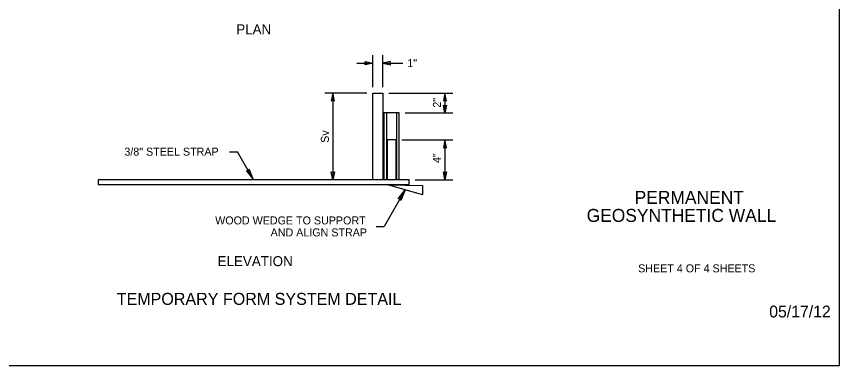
# Model space of a CAD drawing. Extents: x 99862 to 103151, y 100000 to 111076.
# Drawn here: x 101506 to 103151, y 109000 to 109698 of the extents above; entities that cross this region are included whole.
import ezdxf

# ---------------------------------------------------------------- set-up
doc = ezdxf.new("R2010")
doc.units = 0
for name, color, linetype in [('Level 1', 7, 'Continuous'), ('Level 15', 7, 'Continuous'), ('Level 20', 7, 'Continuous'), ('Level 24', 7, 'Continuous'), ('Level 36', 7, 'Continuous'), ('Level 62', 7, 'Continuous')]:
    doc.layers.add(name, color=color, linetype=linetype)

msp = doc.modelspace()

# ---------------------------------------------------------------- linework, layer by layer
at = {"layer": 'Level 1'}
msp.add_lwpolyline([(99862, 108999.5), (103151, 108999.5), (103151, 111075.5), (99862, 111075.5)], close=True, dxfattribs=at)
at = {"layer": 'Level 15'}
for p, q in [((102218.7, 109556.4), (102218.7, 109620.4)), ((102238.4, 109556.4), (102238.4, 109620.4)), ((102186.7, 109604.4), (102218.7, 109604.4)), ((102238.4, 109604.4), (102278.4, 109604.4)), ((102206.7, 109544.4), (102122.7, 109544.4)), ((102138.7, 109544.4), (102138.7, 109371)), ((102250.4, 109544.4), (102378.5, 109544.4)), ((102362.5, 109544.4), (102362.5, 109504.8)), ((102283.4, 109504.8), (102378.5, 109504.8)), ((102276.5, 109450.8), (102378.5, 109450.8)), ((102362.5, 109450.8), (102362.5, 109371)), ((101931.9, 109427.3), (101947.9, 109427.3)), ((101980.4, 109371), (101947.9, 109427.3)), ((102303.1, 109371), (102378.5, 109371)), ((102283.1, 109351), (102240.9, 109277.8)), ((102224.9, 109277.8), (102240.9, 109277.8))]:
    msp.add_line(p, q, dxfattribs=at)
for points in [[(102218.7, 109604.4), (102203, 109601.3), (102203.7, 109604.4), (102203, 109607.5)], [(102238.4, 109604.4), (102254.1, 109601.3), (102253.4, 109604.4), (102254.1, 109607.5)], [(102138.7, 109544.4), (102135.6, 109528.7), (102138.7, 109529.4), (102141.8, 109528.7)], [(102362.5, 109544.4), (102359.5, 109528.7), (102362.5, 109529.4), (102365.6, 109528.7)], [(102362.5, 109504.8), (102359.5, 109520.6), (102362.5, 109519.8), (102365.6, 109520.6)], [(102362.5, 109450.8), (102359.5, 109435), (102362.5, 109435.8), (102365.6, 109435)], [(101980.4, 109371), (101971.6, 109392.3), (101969.5, 109389.9), (101966.4, 109389.3)], [(102138.7, 109371), (102135.6, 109386.7), (102138.7, 109386), (102141.8, 109386.7)], [(102362.5, 109371), (102359.5, 109386.7), (102362.5, 109386), (102365.6, 109386.7)], [(102283.1, 109351), (102274.3, 109329.7), (102272.2, 109332.1), (102269.1, 109332.7)]]:
    msp.add_lwpolyline(points, close=True, dxfattribs=at)
at = {"layer": 'Level 24'}
for points in [[(102218.7, 109371), (102218.7, 109544.4), (102238.4, 109544.4), (102238.4, 109371)], [(102271.4, 109371), (102271.4, 109504.8), (102240.3, 109504.8), (102240.3, 109371)]]:
    msp.add_lwpolyline(points, dxfattribs=at)
for points in [[(102291.1, 109361.3), (102291.1, 109371), (101669.8, 109371), (101669.8, 109361.3)], [(102248.7, 109361.2), (102317.5, 109359.6), (102317.5, 109340.7)]]:
    msp.add_lwpolyline(points, close=True, dxfattribs=at)
at = {"layer": 'Level 36'}
for p, q in [((102246, 109504.8), (102246, 109371)), ((102265.7, 109504.8), (102265.7, 109371)), ((102264.5, 109450.8), (102247.2, 109450.8)), ((102247.2, 109450.8), (102247.2, 109371)), ((102264.5, 109450.8), (102264.5, 109371))]:
    msp.add_line(p, q, dxfattribs=at)

# ---------------------------------------------------------------- texts
at = {"layer": 'Level 1'}
msp.add_text('05/17/12', height=23.62, dxfattribs=at).set_placement((103010.5, 109095.8))
at = {"layer": 'Level 20'}
for s, height, p in [('PLAN', 20, (101945.7, 109662)), ('1"', 16, (102287.4, 109596.4)), ('3/8" STEEL STRAP', 16, (101722.1, 109419.3)), ('WOOD WEDGE TO SUPPORT', 16, (101903.5, 109281.8)), ('AND ALIGN STRAP', 16, (102014.3, 109257.8)), ('ELEVATION', 20, (101908.4, 109198.3)), ('TEMPORARY FORM SYSTEM DETAIL', 24, (101706.8, 109120.9))]:
    msp.add_text(s, height=height, dxfattribs=at).set_placement(p)
for s, p in [('2"', (102354.5, 109515.3)), ('Sv', (102130.7, 109445)), ('4"', (102354.5, 109404.5))]:
    msp.add_text(s, height=16, rotation=90, dxfattribs=at).set_placement(p)
at = {"layer": 'Level 62'}
for s, height, p in [('PERMANENT', 26, (102741.6, 109322.8)), ('GEOSYNTHETIC WALL', 26, (102645.7, 109286.8)), ('SHEET 4 OF 4 SHEETS', 16, (102748.6, 109185.9))]:
    msp.add_text(s, height=height, dxfattribs=at).set_placement(p)

doc.saveas('drawing.dxf')
